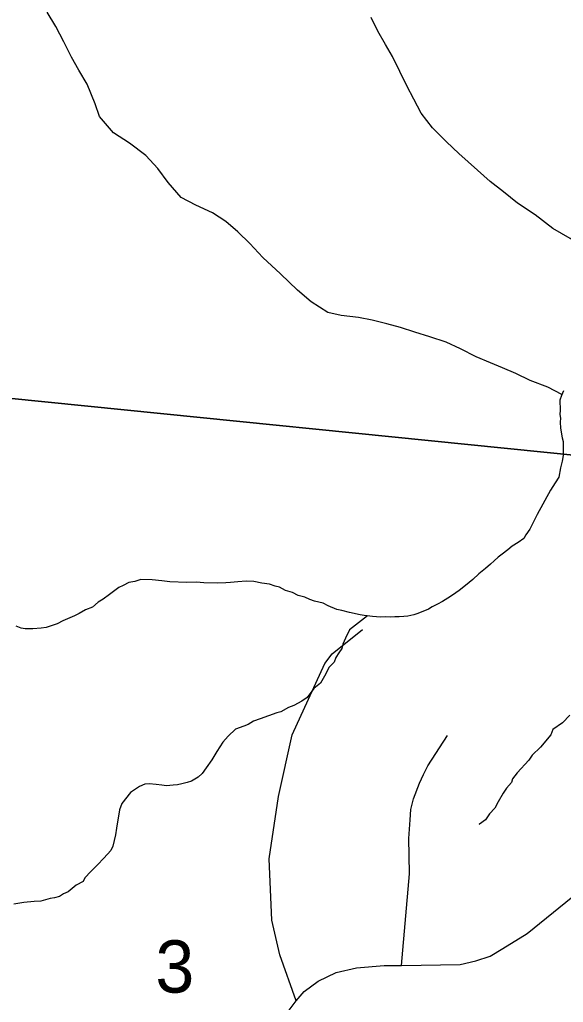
# Model space of a CAD drawing. Extents: x -8.2 to 38.5, y -0.1 to 21.9.
# Drawn here: x 3.122 to 3.557, y 17.891 to 18.678 of the extents above; entities that cross this region are included whole.
import ezdxf

# ---------------------------------------------------------------- set-up
doc = ezdxf.new("R2010")
doc.units = 0
for name, color, linetype in [('GM_X_Adjacent_County_Text', 7, 'Continuous'), ('GM_X_County_Road_Text', 7, 'Continuous'), ('GM_X_Minor_River', 7, 'Continuous'), ('GM_X_Township_Subdivision_Text', 7, 'Continuous'), ('GM_X_Township_Text', 7, 'Continuous')]:
    doc.layers.add(name, color=color, linetype=linetype)

msp = doc.modelspace()

# ---------------------------------------------------------------- linework, layer by layer
at = {"layer": 'GM_X_Adjacent_County_Text'}
msp.add_lwpolyline([(3.94314, 19.29912), (3.84833, 18.30047), (2.83734, 18.40237), (2.94081, 19.38227)], close=True, dxfattribs=at)
msp.add_lwpolyline([(2.87221, 17.38985), (2.73536, 17.40463), (2.83734, 18.40237), (3.84833, 18.30047), (3.75128, 17.38985)], dxfattribs=at)
at = {"layer": 'GM_X_Minor_River'}
for points in [[(3.55589, 18.37749), (3.54459, 18.3835), (3.53066, 18.38879), (3.51901, 18.3944), (3.50848, 18.39884), (3.4987, 18.40288), (3.48742, 18.40772), (3.47465, 18.41412), (3.46338, 18.41934), (3.45019, 18.42384), (3.43812, 18.42756), (3.42681, 18.43126), (3.41586, 18.43419), (3.40415, 18.43714), (3.39319, 18.4393), (3.37916, 18.44079), (3.36859, 18.44333), (3.35511, 18.45164), (3.34432, 18.46104), (3.33058, 18.4743), (3.31645, 18.4872), (3.30609, 18.49848), (3.29643, 18.50785), (3.28675, 18.51607), (3.27629, 18.52317), (3.26275, 18.52921), (3.25112, 18.5352), (3.24077, 18.54724), (3.2323, 18.55848), (3.22268, 18.56898), (3.20962, 18.57881), (3.1969, 18.58711), (3.18582, 18.60031), (3.18226, 18.61028), (3.1758, 18.62603), (3.16924, 18.63723), (3.16341, 18.64763), (3.15725, 18.65996), (3.15071, 18.67229), (3.14377, 18.68387)], [(3.61347, 18.45707), (3.60398, 18.46649), (3.59667, 18.47846), (3.58555, 18.48976), (3.57316, 18.49615), (3.56268, 18.50249), (3.54881, 18.51044), (3.53464, 18.52143), (3.52043, 18.53091), (3.50925, 18.53993), (3.49843, 18.54818), (3.48839, 18.55717), (3.47351, 18.57046), (3.46348, 18.57984), (3.45235, 18.59114), (3.44313, 18.60277), (3.43733, 18.61395), (3.43189, 18.62473), (3.42609, 18.63628), (3.4203, 18.64821), (3.41483, 18.65785), (3.40863, 18.66865), (3.4032, 18.67944)], [(3.5572, 18.38054), (3.55558, 18.37677), (3.55434, 18.373), (3.5545, 18.365), (3.55441, 18.36157), (3.55471, 18.35852), (3.55462, 18.35547), (3.55487, 18.35051), (3.55618, 18.34286), (3.55686, 18.3398), (3.55707, 18.33332), (3.55694, 18.32875), (3.55606, 18.3242), (3.55477, 18.31891), (3.55343, 18.31133), (3.55064, 18.30684), (3.54668, 18.30086), (3.53627, 18.28134), (3.53225, 18.27346), (3.53025, 18.26971), (3.52708, 18.26523), (3.52548, 18.26222), (3.52083, 18.25892), (3.51619, 18.25601), (3.51268, 18.25306), (3.50803, 18.24976), (3.50492, 18.24718), (3.5018, 18.24422), (3.49868, 18.24164), (3.49479, 18.23833), (3.48935, 18.23391), (3.48466, 18.22947), (3.47883, 18.22468), (3.47378, 18.22063), (3.46836, 18.21698)], [(3.46836, 18.21698), (3.46448, 18.21442), (3.46023, 18.21187), (3.45637, 18.20969), (3.45213, 18.20753), (3.44904, 18.20571), (3.44057, 18.20214), (3.4375, 18.20108), (3.43253, 18.20008), (3.42948, 18.19978), (3.42567, 18.19951), (3.42225, 18.1996), (3.41844, 18.19933), (3.41502, 18.19942), (3.41083, 18.19916), (3.40438, 18.19972), (3.39756, 18.20067), (3.39453, 18.20114), (3.38584, 18.2029), (3.3798, 18.2046), (3.37564, 18.20548), (3.36887, 18.20833), (3.36474, 18.21035), (3.35794, 18.21206), (3.35417, 18.21331), (3.35005, 18.21533), (3.34476, 18.21662), (3.34026, 18.21903), (3.3346, 18.22071), (3.32972, 18.22313), (3.32632, 18.22399), (3.3218, 18.22564), (3.31574, 18.22657), (3.30931, 18.22789), (3.30323, 18.22806), (3.29638, 18.22749), (3.29065, 18.22689), (3.28684, 18.22662), (3.28038, 18.22642), (3.26935, 18.22673), (3.26328, 18.22728), (3.25567, 18.22711), (3.242, 18.22749), (3.23556, 18.22843), (3.22797, 18.22902), (3.21885, 18.22928), (3.21387, 18.2279), (3.20927, 18.22688), (3.20465, 18.22472), (3.20118, 18.22292), (3.19381, 18.21741), (3.18877, 18.21374), (3.18451, 18.2112), (3.18022, 18.20713), (3.17446, 18.205), (3.16944, 18.2021), (3.16558, 18.2003), (3.15635, 18.19637), (3.15172, 18.19383), (3.1429, 18.19103), (3.13908, 18.19038), (3.13221, 18.18981), (3.12614, 18.18998), (3.12311, 18.19044), (3.11897, 18.19208)], [(3.4003, 18.20029), (3.38584, 18.18919), (3.38262, 18.18243), (3.38058, 18.17754), (3.37973, 18.17413), (3.37736, 18.17077), (3.37498, 18.16703), (3.37373, 18.16326), (3.36943, 18.1588), (3.36702, 18.15392), (3.36263, 18.14643), (3.35719, 18.14201), (3.35205, 18.13492), (3.34779, 18.13199), (3.34122, 18.12837), (3.337, 18.12696), (3.33082, 18.12332), (3.32776, 18.12265), (3.31432, 18.11769), (3.30895, 18.11594), (3.30469, 18.11339), (3.30123, 18.11196), (3.2947, 18.10948), (3.28884, 18.10393), (3.28453, 18.0991), (3.27977, 18.09162), (3.27578, 18.08487), (3.27105, 18.07853), (3.26788, 18.07405), (3.26476, 18.07109), (3.25935, 18.06781), (3.2559, 18.06677), (3.25168, 18.06574), (3.24824, 18.06508), (3.24481, 18.06479), (3.23947, 18.06418), (3.23568, 18.06467), (3.23113, 18.06517), (3.22545, 18.06571), (3.22202, 18.06543), (3.21778, 18.06364), (3.21043, 18.0589), (3.20372, 18.04994), (3.20169, 18.04505), (3.19938, 18.03026), (3.19848, 18.02496), (3.19633, 18.01587), (3.19472, 18.01249), (3.18923, 18.00617), (3.18414, 18.00098), (3.17867, 17.99542), (3.17397, 17.9906), (3.17275, 17.98759), (3.16697, 17.9847), (3.16073, 17.97917), (3.15689, 17.97775), (3.15379, 17.97555), (3.14958, 17.97453), (3.14614, 17.97386), (3.13886, 17.97178), (3.13353, 17.97155), (3.12514, 17.97064), (3.11712, 17.96934)], [(3.56234, 18.12066), (3.55647, 18.11473), (3.54872, 18.10924), (3.54709, 18.1051), (3.53883, 18.09504), (3.53219, 18.08876), (3.52942, 18.08464), (3.52002, 18.07462), (3.51647, 18.06977), (3.51563, 18.06675), (3.5117, 18.06229), (3.50893, 18.05818), (3.50494, 18.05143), (3.50214, 18.04618), (3.49784, 18.04173), (3.49466, 18.03687), (3.49001, 18.03357), (3.48935, 18.03317)]]:
    msp.add_lwpolyline(points, dxfattribs=at)
at = {"layer": 'GM_X_Township_Subdivision_Text'}
for points in [[(3.34318, 17.89184), (3.33, 17.9287), (3.32379, 17.95655), (3.32145, 18.00558), (3.32898, 18.05554), (3.33991, 18.10503), (3.36606, 18.16204), (3.37206, 18.16985), (3.39631, 18.18922)], [(3.42756, 17.92018), (3.43404, 17.9938), (3.43364, 18.0084), (3.43348, 18.02186), (3.43453, 18.03695), (3.4351, 18.04531), (3.43705, 18.05366), (3.44183, 18.06632), (3.445, 18.07321), (3.44865, 18.08019), (3.46447, 18.10437)]]:
    msp.add_lwpolyline(points, dxfattribs=at)
at = {"layer": 'GM_X_Township_Text'}
msp.add_lwpolyline([(3.33769, 17.88445), (3.34318, 17.89184), (3.34951, 17.8994), (3.36071, 17.90768), (3.37515, 17.91466), (3.39154, 17.91839), (3.41376, 17.92018), (3.42756, 17.92018), (3.47461, 17.92115), (3.48694, 17.9239), (3.49846, 17.9278), (3.50868, 17.93396), (3.52818, 17.94581), (3.57465, 17.98341)], dxfattribs=at)

# ---------------------------------------------------------------- texts
at = {"layer": 'GM_X_County_Road_Text'}
msp.add_text('3', height=0.04186, rotation=0.00001, dxfattribs=at).set_placement((3.23047, 17.89856))

doc.saveas('drawing.dxf')
